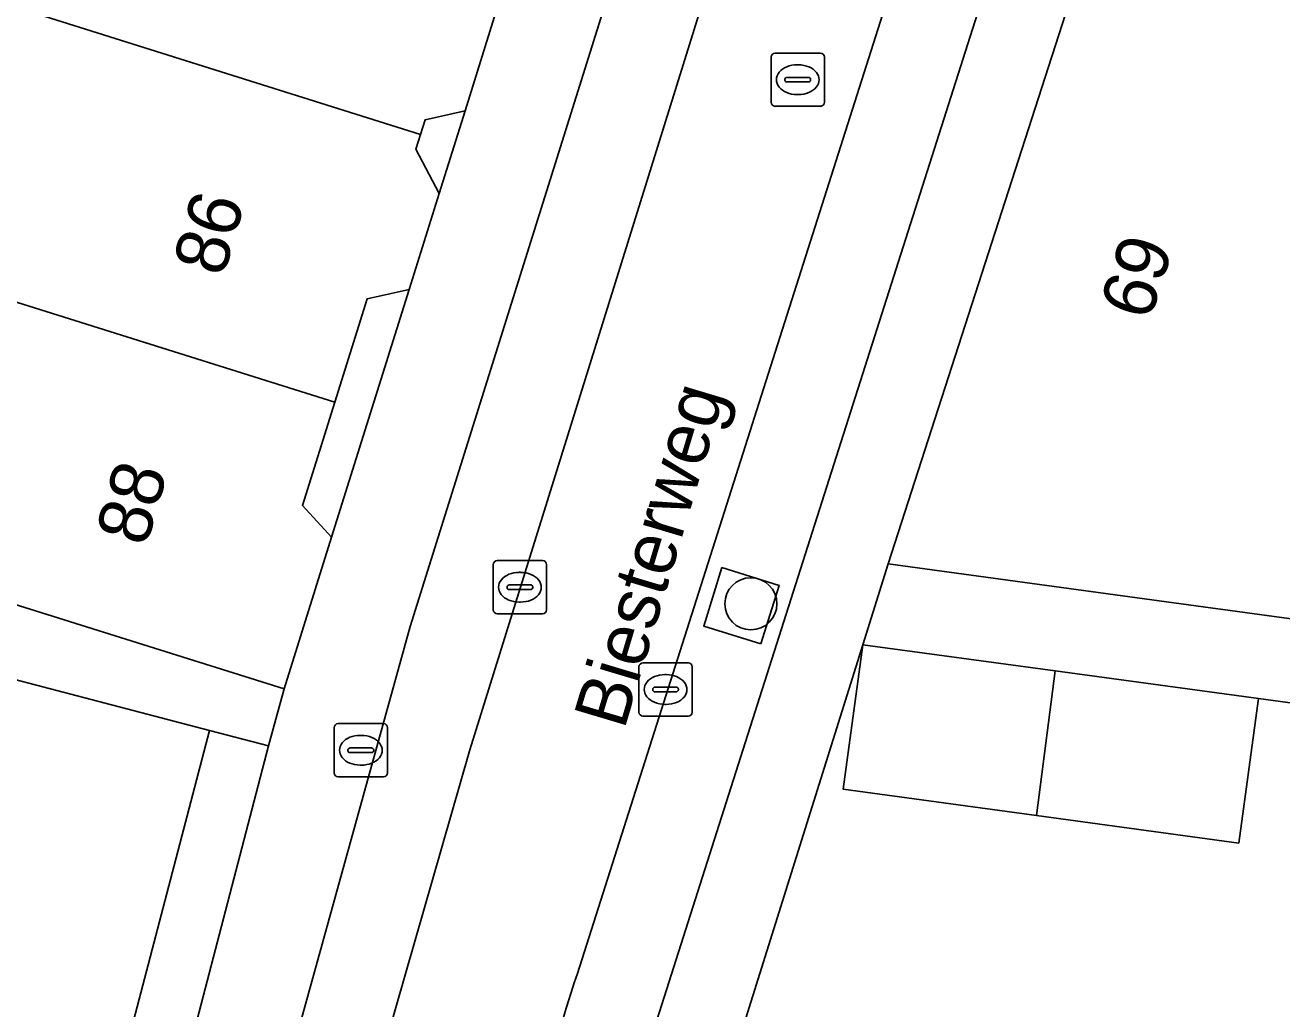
# Model space of a CAD drawing. Extents: x 161838 to 162344, y 381620 to 382160.
# Drawn here: x 161912.46 to 161936.08, y 381728.55 to 381747.04 of the extents above; entities that cross this region are included whole.
import ezdxf

# ---------------------------------------------------------------- set-up
doc = ezdxf.new("R2010")
doc.units = 0
for name, color, linetype in [('IMGEO_Boom', 7, 'Continuous'), ('IMGEO_Brandkraan', 7, 'Continuous'), ('IMGEO_Erf', 7, 'Continuous'), ('IMGEO_Groenvoorziening', 7, 'Continuous'), ('IMGEO_Hek', 7, 'Continuous'), ('IMGEO_Kolk', 7, 'Continuous'), ('IMGEO_Muur', 7, 'Continuous'), ('IMGEO_Openbare_ruimte_label', 7, 'Continuous'), ('IMGEO_Pand', 7, 'Continuous'), ('IMGEO_Pand_nummerreeks', 7, 'Continuous'), ('IMGEO_Parkeervlak_open', 7, 'Continuous'), ('IMGEO_Rijbaan_lokaal_open', 7, 'Continuous'), ('IMGEO_Rioolput', 7, 'Continuous'), ('IMGEO_Voetpad_open', 7, 'Continuous')]:
    doc.layers.add(name, color=color, linetype=linetype)

msp = doc.modelspace()

# ---------------------------------------------------------------- linework, layer by layer
at = {"layer": 'IMGEO_Boom'}
msp.add_circle((161926.097, 381736.168), 0.489, dxfattribs=at)
at = {"layer": 'IMGEO_Brandkraan'}
for p, q in [((161918.341, 381733.915), (161919.193, 381733.915)), ((161918.266, 381732.989), (161918.266, 381733.841)), ((161918.754, 381733.695), (161918.779, 381733.695)), ((161919.267, 381733.841), (161919.267, 381732.989)), ((161918.525, 381733.409), (161918.525, 381733.421)), ((161918.963, 381733.372), (161918.565, 381733.372)), ((161918.568, 381733.458), (161918.966, 381733.458)), ((161919.009, 381733.421), (161919.009, 381733.409)), ((161918.777, 381733.135), (161918.752, 381733.135)), ((161919.193, 381732.915), (161918.341, 381732.915))]:
    msp.add_line(p, q, dxfattribs=at)
for points in [[(161918.341, 381733.915), (161919.193, 381733.915)], [(161918.266, 381732.989), (161918.266, 381733.841)], [(161919.267, 381733.841), (161919.267, 381732.989)], [(161919.193, 381732.915), (161918.341, 381732.915)]]:
    msp.add_lwpolyline(points, dxfattribs=at)
for centre, radius, start, end in [((161918.343, 381733.839), 0.0765, 91.552, 178.448), ((161918.343, 381733.839), 0.0765, 91.552, 178.448), ((161919.191, 381733.839), 0.0765, 1.552, 88.448), ((161919.191, 381733.839), 0.0765, 1.552, 88.448), ((161918.565, 381733.418), 0.0403, 85.8775, 175.7526), ((161918.562, 381733.408), 0.0366, 178.938, 274.7102), ((161918.966, 381733.415), 0.043, 264.8664, 352.4533), ((161918.97, 381733.42), 0.0386, 1.7309, 96.639), ((161918.343, 381732.991), 0.0765, 181.552, 268.448), ((161918.343, 381732.991), 0.0765, 181.552, 268.448), ((161919.191, 381732.991), 0.0765, 271.552, 358.448), ((161919.191, 381732.991), 0.0765, 271.552, 358.448)]:
    msp.add_arc(centre, radius, start, end, dxfattribs=at)
for centre, major_axis, ratio, start_param, end_param in [((161918.753, 381733.415), (-0.387, 0.002), 0.722429, 4.712389, 7.853982), ((161918.778, 381733.415), (-0.39, 0.002), 0.717154, 1.570796, 4.712389)]:
    msp.add_ellipse(centre, major_axis=major_axis, ratio=ratio, start_param=start_param, end_param=end_param, dxfattribs=at)
at = {"layer": 'IMGEO_Erf'}
for points in [[(161919.889, 381744.99), (161919.803, 381744.714), (161920.239, 381743.88), (161920.725, 381745.432), (161919.975, 381745.264)], [(161919.673, 381742.076), (161918.886, 381741.9), (161918.278, 381739.958), (161917.669, 381738.015), (161918.217, 381737.419)]]:
    msp.add_lwpolyline(points, close=True, dxfattribs=at)
msp.add_lwpolyline([(161938.349, 381734.019), (161935.636, 381734.387), (161935.266, 381731.67), (161931.464, 381732.187), (161927.834, 381732.681), (161928.204, 381735.395), (161925.447, 381726.604), (161924.676, 381720.871), (161927.632, 381720.509), (161928.32, 381725.886), (161930.605, 381725.594), (161933.317, 381725.247), (161932.659, 381720.24), (161935.255, 381719.901), (161937.893, 381719.556)], dxfattribs=at)
at = {"layer": 'IMGEO_Groenvoorziening'}
msp.add_lwpolyline([(161926.287, 381735.415), (161926.628, 381736.514), (161925.552, 381736.848), (161925.211, 381735.749)], close=True, dxfattribs=at)
at = {"layer": 'IMGEO_Hek'}
msp.add_lwpolyline([(161917.032, 381733.501), (161914.271, 381722.897)], dxfattribs=at)
at = {"layer": 'IMGEO_Kolk'}
for p, q in [((161921.331, 381736.979), (161922.183, 381736.979)), ((161921.256, 381736.053), (161921.256, 381736.905)), ((161921.744, 381736.759), (161921.769, 381736.759)), ((161922.257, 381736.905), (161922.257, 381736.053)), ((161921.515, 381736.473), (161921.515, 381736.485)), ((161921.558, 381736.522), (161921.956, 381736.522)), ((161921.999, 381736.485), (161921.999, 381736.473)), ((161921.953, 381736.436), (161921.555, 381736.436)), ((161922.183, 381735.979), (161921.331, 381735.979)), ((161921.767, 381736.199), (161921.742, 381736.199)), ((161924.069, 381735.057), (161924.921, 381735.057)), ((161923.994, 381734.131), (161923.994, 381734.983)), ((161924.482, 381734.837), (161924.507, 381734.837)), ((161924.995, 381734.983), (161924.995, 381734.131)), ((161924.253, 381734.551), (161924.253, 381734.563)), ((161924.296, 381734.6), (161924.694, 381734.6)), ((161924.737, 381734.563), (161924.737, 381734.551)), ((161924.691, 381734.514), (161924.293, 381734.514)), ((161924.505, 381734.277), (161924.48, 381734.277)), ((161924.921, 381734.057), (161924.069, 381734.057))]:
    msp.add_line(p, q, dxfattribs=at)
for points in [[(161921.331, 381736.979), (161922.183, 381736.979)], [(161921.256, 381736.053), (161921.256, 381736.905)], [(161922.257, 381736.905), (161922.257, 381736.053)], [(161922.183, 381735.979), (161921.331, 381735.979)], [(161924.069, 381735.057), (161924.921, 381735.057)], [(161923.994, 381734.131), (161923.994, 381734.983)], [(161924.995, 381734.983), (161924.995, 381734.131)], [(161924.921, 381734.057), (161924.069, 381734.057)]]:
    msp.add_lwpolyline(points, dxfattribs=at)
for centre, radius, start, end in [((161921.333, 381736.903), 0.0765, 91.552, 178.448), ((161921.333, 381736.903), 0.0765, 91.552, 178.448), ((161922.181, 381736.903), 0.0765, 1.552, 88.448), ((161922.181, 381736.903), 0.0765, 1.552, 88.448), ((161921.555, 381736.482), 0.0403, 85.8775, 175.7526), ((161921.552, 381736.472), 0.0366, 178.938, 274.7102), ((161921.956, 381736.479), 0.043, 264.8664, 352.4533), ((161921.96, 381736.484), 0.0386, 1.7309, 96.639), ((161921.333, 381736.055), 0.0765, 181.552, 268.448), ((161921.333, 381736.055), 0.0765, 181.552, 268.448), ((161922.181, 381736.055), 0.0765, 271.552, 358.448), ((161922.181, 381736.055), 0.0765, 271.552, 358.448), ((161924.071, 381734.981), 0.0765, 91.552, 178.448), ((161924.071, 381734.981), 0.0765, 91.552, 178.448), ((161924.919, 381734.981), 0.0765, 1.552, 88.448), ((161924.919, 381734.981), 0.0765, 1.552, 88.448), ((161924.293, 381734.56), 0.0403, 85.8775, 175.7526), ((161924.29, 381734.55), 0.0366, 178.938, 274.7102), ((161924.694, 381734.557), 0.043, 264.8664, 352.4533), ((161924.698, 381734.562), 0.0386, 1.7309, 96.639), ((161924.071, 381734.133), 0.0765, 181.552, 268.448), ((161924.071, 381734.133), 0.0765, 181.552, 268.448), ((161924.919, 381734.133), 0.0765, 271.552, 358.448), ((161924.919, 381734.133), 0.0765, 271.552, 358.448)]:
    msp.add_arc(centre, radius, start, end, dxfattribs=at)
for centre, major_axis, ratio, start_param, end_param in [((161921.743, 381736.479), (-0.387, 0.002), 0.722429, 4.712389, 7.853982), ((161921.768, 381736.479), (-0.39, 0.002), 0.717154, 1.570796, 4.712389), ((161924.481, 381734.557), (-0.387, 0.002), 0.722429, 4.712389, 7.853982), ((161924.506, 381734.557), (-0.39, 0.002), 0.717154, 1.570796, 4.712389)]:
    msp.add_ellipse(centre, major_axis=major_axis, ratio=ratio, start_param=start_param, end_param=end_param, dxfattribs=at)
at = {"layer": 'IMGEO_Muur'}
msp.add_lwpolyline([(161924.676, 381720.871), (161925.447, 381726.604), (161928.204, 381735.395)], dxfattribs=at)
at = {"layer": 'IMGEO_Pand'}
for points in [[(161943.773, 381771.406), (161941.27, 381771.689), (161940.656, 381766.246), (161939.055, 381754.703), (161940.747, 381754.512), (161940.179, 381750), (161940.003, 381748.598), (161932.761, 381749.584), (161928.68, 381736.917), (161933.635, 381736.242), (161961.501, 381732.448), (161962.379, 381738.634), (161963.918, 381750), (161965.98, 381765.232), (161966.661, 381770.185), (161958.302, 381771.128), (161958.15, 381769.783)], [(161911.501, 381747.601), (161911.931, 381747.484), (161919.889, 381744.99), (161919.975, 381745.264), (161920.725, 381745.432), (161921.338, 381747.387), (161920.799, 381747.972), (161921.4, 381749.878), (161921.01, 381750), (161913.46, 381752.366), (161913.031, 381752.482), (161912.253, 381750)], [(161919.803, 381744.714), (161919.889, 381744.99), (161911.931, 381747.484), (161911.501, 381747.601), (161910.729, 381745.136), (161907.818, 381745.978), (161907.547, 381745.04), (161900.603, 381746.898), (161900.186, 381745.198), (161904.185, 381744.088), (161904.269, 381744.065), (161907.187, 381743.221), (161910.351, 381742.442), (161918.278, 381739.958), (161918.886, 381741.9), (161919.673, 381742.076), (161920.239, 381743.88)], [(161904.185, 381744.088), (161904.127, 381743.854), (161904.005, 381743.36), (161903.668, 381741.987), (161906.465, 381741.301), (161906.262, 381740.597), (161909.054, 381739.79), (161908.304, 381737.397), (161912.554, 381736.066), (161917.325, 381734.571), (161918.217, 381737.419), (161917.669, 381738.015), (161918.278, 381739.958), (161910.351, 381742.442), (161907.187, 381743.221), (161904.269, 381744.065)], [(161931.464, 381732.187), (161931.818, 381734.905), (161928.204, 381735.395), (161927.834, 381732.681)], [(161931.464, 381732.187), (161935.266, 381731.67), (161935.636, 381734.387), (161931.818, 381734.905)]]:
    msp.add_lwpolyline(points, close=True, dxfattribs=at)
msp.add_lwpolyline([(161912.06, 381719.035), (161913.133, 381723.134), (161915.922, 381733.787), (161911.085, 381735.053)], dxfattribs=at)
at = {"layer": 'IMGEO_Parkeervlak_open'}
for points in [[(161930.019, 381773.8), (161929.028, 381768.381), (161928.167, 381764.412), (161925.871, 381755.689), (161925.028, 381752.783), (161924.159, 381750), (161919.692, 381735.743), (161915.985, 381722.354)], [(161916.883, 381719.321), (161919.084, 381727.401), (161920.816, 381733.424), (161927.557, 381755.075), (161928.855, 381760.062)], [(161929.449, 381750), (161922.839, 381729.219)], [(161922.974, 381718.936), (161923.837, 381725.942), (161924.196, 381727.931), (161931.251, 381750.082)]]:
    msp.add_lwpolyline(points, dxfattribs=at)
msp.add_lwpolyline([(161926.287, 381735.415), (161925.211, 381735.749), (161925.552, 381736.848), (161926.628, 381736.514)], close=True, dxfattribs=at)
msp.add_arc((161934.786, 381724.996), 12.672, 160.5333, 174.0891, dxfattribs=at)
at = {"layer": 'IMGEO_Rijbaan_lokaal_open'}
for points in [[(161928.855, 381760.062), (161927.557, 381755.075), (161920.816, 381733.424), (161919.084, 381727.401), (161916.883, 381719.321), (161916.695, 381718.702), (161921.068, 381717.499), (161922.182, 381726.301)], [(161922.839, 381729.219), (161929.449, 381750)]]:
    msp.add_lwpolyline(points, dxfattribs=at)
msp.add_arc((161934.786, 381724.996), 12.672, 160.5333, 174.0891, dxfattribs=at)
at = {"layer": 'IMGEO_Rioolput'}
for p, q in [((161926.478, 381745.591), (161926.478, 381746.443)), ((161926.553, 381746.517), (161927.405, 381746.517)), ((161927.479, 381746.443), (161927.479, 381745.591)), ((161926.966, 381746.297), (161926.991, 381746.297)), ((161926.737, 381746.011), (161926.737, 381746.023)), ((161927.175, 381745.974), (161926.777, 381745.974)), ((161926.78, 381746.06), (161927.178, 381746.06)), ((161927.221, 381746.023), (161927.221, 381746.011)), ((161926.989, 381745.737), (161926.964, 381745.737)), ((161927.405, 381745.517), (161926.553, 381745.517))]:
    msp.add_line(p, q, dxfattribs=at)
for points in [[(161926.478, 381745.591), (161926.478, 381746.443)], [(161926.553, 381746.517), (161927.405, 381746.517)], [(161927.479, 381746.443), (161927.479, 381745.591)], [(161927.405, 381745.517), (161926.553, 381745.517)]]:
    msp.add_lwpolyline(points, dxfattribs=at)
for centre, radius, start, end in [((161926.555, 381746.441), 0.0765, 91.552, 178.448), ((161926.555, 381746.441), 0.0765, 91.552, 178.448), ((161927.403, 381746.441), 0.0765, 1.552, 88.448), ((161927.403, 381746.441), 0.0765, 1.552, 88.448), ((161926.777, 381746.02), 0.0403, 85.8775, 175.7526), ((161926.774, 381746.01), 0.0366, 178.938, 274.7102), ((161927.178, 381746.017), 0.043, 264.8664, 352.4533), ((161927.182, 381746.022), 0.0386, 1.7309, 96.639), ((161926.555, 381745.593), 0.0765, 181.552, 268.448), ((161926.555, 381745.593), 0.0765, 181.552, 268.448), ((161927.403, 381745.593), 0.0765, 271.552, 358.448), ((161927.403, 381745.593), 0.0765, 271.552, 358.448)]:
    msp.add_arc(centre, radius, start, end, dxfattribs=at)
for centre, major_axis, ratio, start_param, end_param in [((161926.965, 381746.017), (-0.387, 0.002), 0.722429, 4.712389, 7.853982), ((161926.99, 381746.017), (-0.39, 0.002), 0.717154, 1.570796, 4.712389)]:
    msp.add_ellipse(centre, major_axis=major_axis, ratio=ratio, start_param=start_param, end_param=end_param, dxfattribs=at)
at = {"layer": 'IMGEO_Voetpad_open'}
for points in [[(161924.676, 381720.871), (161925.447, 381726.604), (161928.204, 381735.395), (161928.68, 381736.917), (161932.761, 381749.584), (161932.874, 381750), (161935.609, 381760.072), (161937.166, 381766.879), (161939.117, 381777.363), (161939.385, 381777.509), (161937.963, 381779.132)], [(161932.238, 381776.158), (161932.346, 381776.852), (161928.936, 381777.521), (161927.949, 381772.425), (161926.809, 381766.533), (161926.758, 381766.342), (161925.266, 381760.778), (161923.832, 381755.432), (161923.772, 381755.207), (161922.777, 381752.053), (161921.338, 381747.387), (161920.725, 381745.432), (161920.239, 381743.88), (161919.673, 381742.076), (161918.217, 381737.419), (161917.325, 381734.571), (161917.032, 381733.501), (161914.271, 381722.897), (161912.504, 381716.211), (161915.172, 381715.818), (161916.534, 381718.098), (161916.581, 381718.326), (161916.695, 381718.702), (161916.883, 381719.321)], [(161915.985, 381722.354), (161919.692, 381735.743), (161924.159, 381750)], [(161931.251, 381750.082), (161924.196, 381727.931), (161923.837, 381725.942), (161922.974, 381718.936)], [(161961.501, 381732.448), (161933.635, 381736.242), (161928.68, 381736.917), (161928.204, 381735.395), (161931.818, 381734.905), (161935.636, 381734.387), (161938.349, 381734.019)]]:
    msp.add_lwpolyline(points, dxfattribs=at)
for points in [[(161895.655, 381738.777), (161896.431, 381738.635), (161896.494, 381738.873), (161911.085, 381735.053), (161915.922, 381733.787), (161917.032, 381733.501), (161917.325, 381734.571), (161912.554, 381736.066), (161908.304, 381737.397), (161898.976, 381740.318), (161900.186, 381745.198), (161900.603, 381746.898), (161902.585, 381754.979), (161899.797, 381755.663), (161896.247, 381741.19)], [(161914.271, 381722.897), (161917.032, 381733.501), (161915.922, 381733.787), (161913.133, 381723.134)]]:
    msp.add_lwpolyline(points, close=True, dxfattribs=at)

# ---------------------------------------------------------------- texts
at = {"layer": 'IMGEO_Openbare_ruimte_label'}
msp.add_text('Biesterweg', height=1, rotation=73.3227, dxfattribs=at).set_placement((161923.715, 381733.782))
at = {"layer": 'IMGEO_Pand_nummerreeks'}
for s, rotation, p in [('86', 74.0319, (161916.182, 381742.289)), ('69', 72.1423, (161933.589, 381741.458)), ('88', 74.0319, (161914.731, 381737.219))]:
    msp.add_text(s, height=1, rotation=rotation, dxfattribs=at).set_placement(p)

doc.saveas('drawing.dxf')
